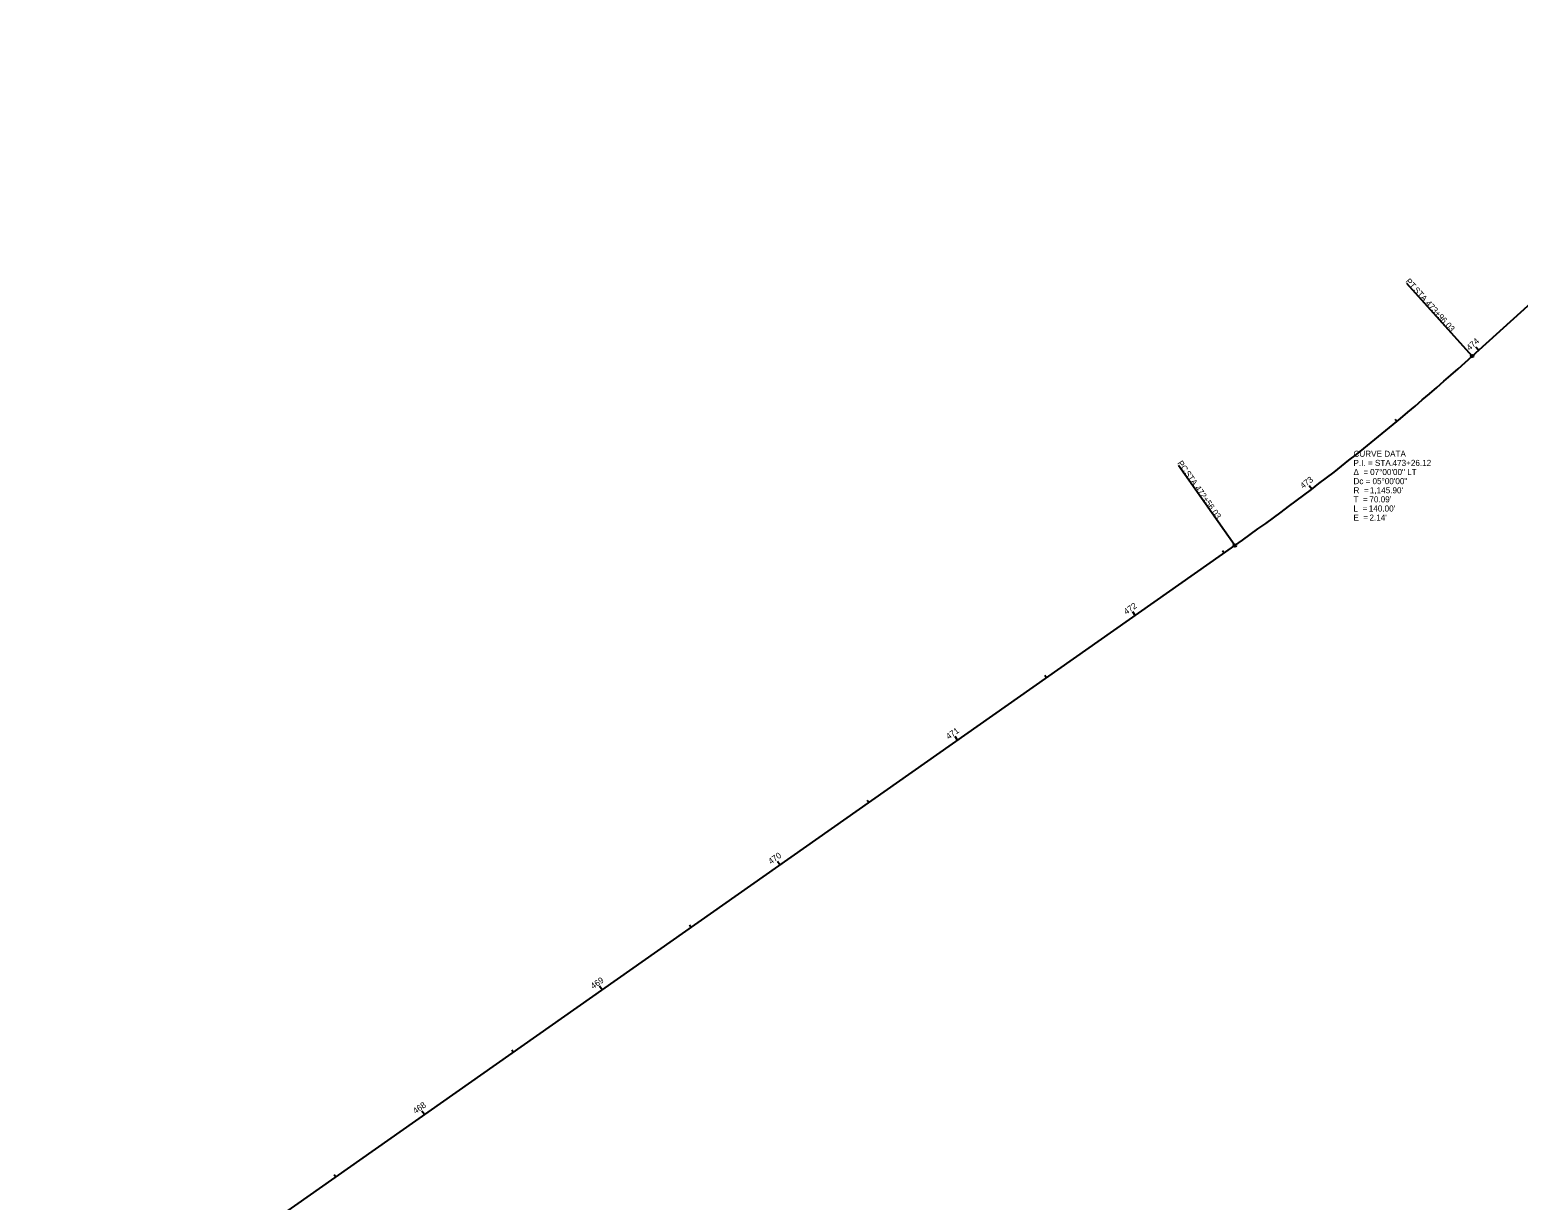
# Model space of a CAD drawing. Extents: x 137787 to 140465, y 476104 to 478286.
# Drawn here: x 138446 to 139132, y 476637 to 477176 of the extents above; entities that cross this region are included whole.
import ezdxf

# ---------------------------------------------------------------- set-up
doc = ezdxf.new("R2010")
doc.units = 0
for name, color, linetype in [('RW_X_CL', 7, 'Continuous'), ('RW_X_Esmt_LA', 7, 'Continuous'), ('RW_X_Esmt_SH', 7, 'Continuous'), ('SC_Scratch1', 7, 'Continuous'), ('SV_P_Mon_Cells_Set', 7, 'Continuous'), ('SV_X_Mon_Cells_Found', 7, 'Continuous'), ('SV_X_Shot_Marker', 7, 'Continuous')]:
    doc.layers.add(name, color=color, linetype=linetype)

msp = doc.modelspace()

# ---------------------------------------------------------------- linework, layer by layer
at = {"layer": 'RW_X_CL'}
for p, q in [((139113.6, 477028.78), (139112.79, 477029.67)), ((139036.78, 476964.8), (139036.05, 476965.76)), ((138955.45, 476906.62), (138954.76, 476907.61)), ((138873.63, 476849.13), (138872.94, 476850.11)), ((138791.81, 476791.64), (138790.66, 476793.28)), ((138709.99, 476734.15), (138709.3, 476735.13)), ((138628.17, 476676.65), (138627.48, 476677.63))]:
    msp.add_line(p, q, dxfattribs=at)
at = {"layer": 'RW_X_Esmt_SH'}
for p, q in [((139110.65, 477026.12), (139080.48, 477059.51)), ((139001.3, 476938.84), (138975.43, 476975.66))]:
    msp.add_line(p, q, dxfattribs=at)
for centre in [(139110.65, 477026.12), (139001.3, 476938.84)]:
    msp.add_circle(centre, 0.6, dxfattribs=at)
at = {"layer": 'SC_Scratch1'}
for p, q in [((139113.6, 477028.78), (139112.26, 477030.26)), ((139075.88, 476995.95), (139075.12, 476996.88)), ((139036.78, 476964.8), (139035.57, 476966.39)), ((138996.36, 476935.37), (138995.67, 476936.35)), ((138955.45, 476906.62), (138954.3, 476908.26)), ((138914.54, 476877.88), (138913.85, 476878.86)), ((138873.63, 476849.13), (138872.48, 476850.77)), ((138832.72, 476820.39), (138832.03, 476821.37)), ((138791.81, 476791.64), (138790.66, 476793.28)), ((138750.9, 476762.89), (138750.21, 476763.87)), ((138709.99, 476734.15), (138708.84, 476735.78)), ((138669.08, 476705.4), (138668.39, 476706.38)), ((138628.17, 476676.65), (138627.02, 476678.29)), ((138587.26, 476647.91), (138586.57, 476648.89))]:
    msp.add_line(p, q, dxfattribs=at)
at = {"layer": 'SV_P_Mon_Cells_Set'}
for p, q in [((139110.65, 477026.12), (140464.06, 478248.77)), ((137814.18, 476104.68), (139001.3, 476938.84))]:
    msp.add_line(p, q, dxfattribs=at)
msp.add_arc((138342.49, 477876.42), 1145.9, 305.09436, 312.09436, dxfattribs=at)
at = {"layer": 'SV_X_Mon_Cells_Found'}
for p, q in [((139110.65, 477026.12), (139080.48, 477059.51)), ((139001.3, 476938.84), (138975.43, 476975.66))]:
    msp.add_line(p, q, dxfattribs=at)
for centre in [(139110.65, 477026.12), (139001.3, 476938.84)]:
    msp.add_circle(centre, 0.6, dxfattribs=at)

# ---------------------------------------------------------------- texts
at = {"layer": 'RW_X_CL'}
msp.add_text('470', height=2.8, rotation=35.09471, dxfattribs=at).set_placement((138787.7, 476791.81))
at = {"layer": 'RW_X_Esmt_LA'}
for s, p in [('CURVE DATA', (139055.97, 476979.68)), ('Δ  = ', (139055.97, 476971.28)), ('P.I. = STA. ', (139055.97, 476975.48)), ('07°00\'00" LT', (139063.62, 476971.28)), ('473+26.12', (139073.96, 476975.48)), ('Dc = ', (139055.97, 476967.08)), ('05°00\'00"', (139064.72, 476967.08)), ('T  = ', (139055.97, 476958.68)), ('R  = ', (139055.97, 476962.88)), ("70.09'", (139063.29, 476958.68)), ("1,145.90'", (139063.51, 476962.88)), ('L  = ', (139055.97, 476954.48)), ('E  = ', (139055.97, 476950.28)), ("140.00'", (139063.01, 476954.48)), ("2.14'", (139063.32, 476950.28))]:
    msp.add_text(s, height=2.8, dxfattribs=at).set_placement(p)
at = {"layer": 'RW_X_Esmt_SH'}
for s, rotation, p in [('PT', 312.09435, (139079.74, 477060.38)), (' STA. ', 312.09435, (139082.66, 477057.15)), ('473+96.03', 312.09435, (139088.91, 477050.23)), ('PC', 305.09436, (138974.73, 476976.72)), (' STA. ', 305.09436, (138977.37, 476972.95)), ('472+56.03', 305.09436, (138982.73, 476965.32))]:
    msp.add_text(s, height=2.8, rotation=rotation, dxfattribs=at).set_placement(p)
at = {"layer": 'SC_Scratch1'}
for s, rotation, p in [('474', 42.09435, (139109.49, 477028.43)), ('473', 37.29284, (139032.72, 476964.85)), ('472', 35.09471, (138951.39, 476906.82)), ('471', 35.09471, (138869.56, 476849.32)), ('470', 35.09471, (138787.7, 476791.81)), ('469', 35.09471, (138705.91, 476734.34)), ('468', 35.09471, (138624.08, 476676.83))]:
    msp.add_text(s, height=2.8, rotation=rotation, dxfattribs=at).set_placement(p)
at = {"layer": 'SV_X_Mon_Cells_Found'}
for s, rotation, p in [('PT', 312.09435, (139079.74, 477060.38)), (' STA. ', 312.09435, (139082.66, 477057.15)), ('473+96.03', 312.09435, (139088.91, 477050.23)), ('PC', 305.09436, (138974.73, 476976.72)), (' STA. ', 305.09436, (138977.37, 476972.95)), ('472+56.03', 305.09436, (138982.73, 476965.32))]:
    msp.add_text(s, height=2.8, rotation=rotation, dxfattribs=at).set_placement(p)
at = {"layer": 'SV_X_Shot_Marker'}
for s, p in [('CURVE DATA', (139055.97, 476979.68)), ('Δ  = ', (139055.97, 476971.28)), ('P.I. = STA. ', (139055.97, 476975.48)), ('07°00\'00" LT', (139063.62, 476971.28)), ('473+26.12', (139073.96, 476975.48)), ('Dc = ', (139055.97, 476967.08)), ('05°00\'00"', (139064.72, 476967.08)), ('T  = ', (139055.97, 476958.68)), ('R  = ', (139055.97, 476962.88)), ("70.09'", (139063.29, 476958.68)), ("1,145.90'", (139063.51, 476962.88)), ('L  = ', (139055.97, 476954.48)), ('E  = ', (139055.97, 476950.28)), ("140.00'", (139063.01, 476954.48)), ("2.14'", (139063.32, 476950.28))]:
    msp.add_text(s, height=2.8, dxfattribs=at).set_placement(p)

doc.saveas('drawing.dxf')
